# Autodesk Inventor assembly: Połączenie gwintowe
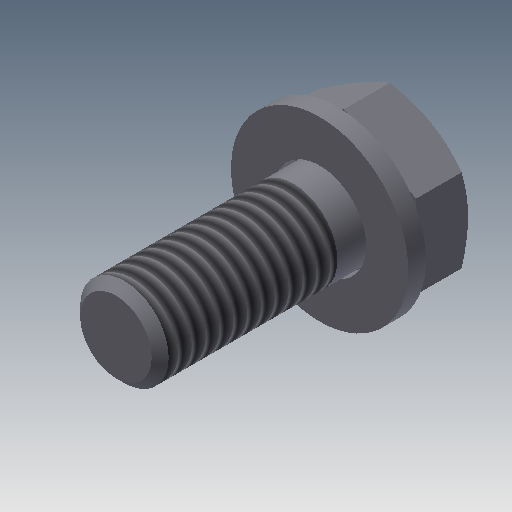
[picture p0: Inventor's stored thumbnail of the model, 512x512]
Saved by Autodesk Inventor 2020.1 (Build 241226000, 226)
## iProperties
Created: 2010-10
Part Number: Połączenie gwintowe
Document SubType Name: Assembly
Designer: F.Stasiak
ClientObjectVersion: 1
Manager: www.cadconsulting.pl
Company: Fabian Stasiak CAD Consulting
Author: F.Stasiak
Subject: Zbiór ćwiczeń. Autodesk Inventor 2020. Kurs podstawowy
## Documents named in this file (3)
- C:\2020_Kurs_podstawowy\R9 Zarządzanie plikami\369-000\Design Accelerator\Połączenie gwintowe9.iam
- C:\2020_Kurs_podstawowy\Zasoby\Content Center Files\pl-PL\ISO 7089\ISO 7089 - 8 - 140 HV(1).ipt
- C:\2020_Kurs_podstawowy\Zasoby\Content Center Files\pl-PL\ISO 4017(1)\ISO 4017 - M8 x 20ISO.ipt
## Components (2 placed, 2 different names)
1. ISO 7089 8 - 140 HV:1
2. ISO 4017 M8 x 20:1
